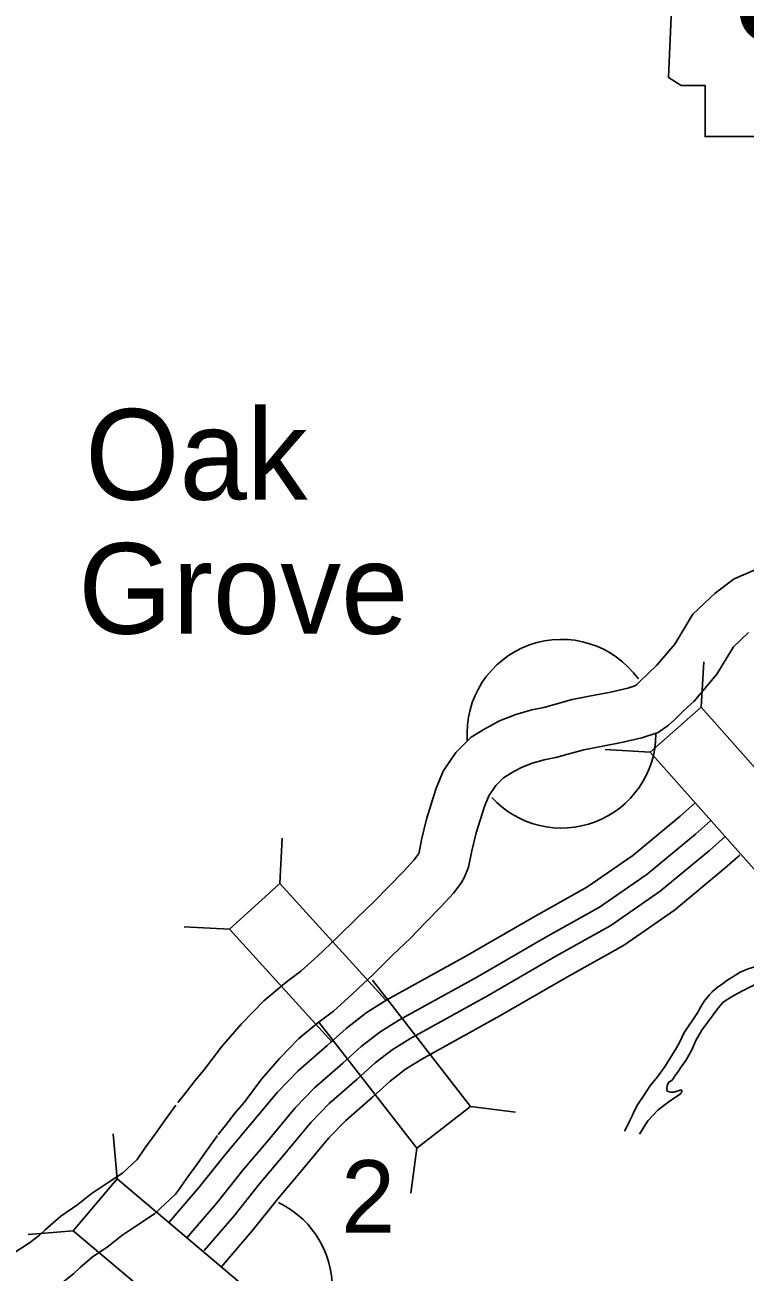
# Model space of a CAD drawing. Extents: x 1373862 to 1377080, y 1164775 to 1170415.
# Drawn here: x 1374523.6 to 1374565.6, y 1170236.6 to 1170309.3 of the extents above; entities that cross this region are included whole.
import ezdxf

# ---------------------------------------------------------------- set-up
doc = ezdxf.new("R2010")
doc.units = 0
doc.layers.add('Default', color=7, linetype='Continuous')

msp = doc.modelspace()

# ---------------------------------------------------------------- linework, layer by layer
at = {"layer": 'Default'}
for p, q in [((1374562.997, 1170269.508), (1374563.156, 1170272.143)), ((1374560.035, 1170266.88), (1374557.399, 1170267.038)), ((1374538.46, 1170259.235), (1374538.588, 1170261.872)), ((1374538.46, 1170259.235), (1374535.528, 1170256.573)), ((1374544.617, 1170252.453), (1374538.46, 1170259.235)), ((1374535.528, 1170256.573), (1374532.891, 1170256.701)), ((1374535.528, 1170256.573), (1374541.501, 1170249.994)), ((1374549.559, 1170246.234), (1374543.849, 1170253.598)), ((1374540.739, 1170251.147), (1374546.43, 1170243.807)), ((1374546.43, 1170243.807), (1374549.559, 1170246.234)), ((1374549.559, 1170246.234), (1374552.178, 1170245.902)), ((1374528.983, 1170242.017), (1374528.761, 1170244.647)), ((1374546.43, 1170243.807), (1374546.098, 1170241.188)), ((1374526.428, 1170238.991), (1374523.798, 1170238.769))]:
    msp.add_line(p, q, dxfattribs=at)
for points in [[(1374560.624, 1170320.259), (1374561.461, 1170314.676), (1374561.089, 1170306.209), (1374561.833, 1170305.744), (1374563.229, 1170305.744), (1374563.229, 1170302.766), (1374574.953, 1170302.766), (1374575.512, 1170303.976), (1374575.325, 1170305.93), (1374575.605, 1170308.163), (1374576.628, 1170309.931), (1374577.279, 1170311.234), (1374578.21, 1170312.629), (1374578.768, 1170314.118), (1374579.233, 1170315.328), (1374580.071, 1170316.351), (1374580.257, 1170317.003), (1374579.885, 1170317.468), (1374577, 1170317.468), (1374577.652, 1170318.77), (1374577.745, 1170319.608), (1374577.359, 1170320.251)], [(1374560.035, 1170266.88), (1374567.917, 1170257.992), (1374570.88, 1170260.619), (1374562.997, 1170269.508)], [(1374538.06, 1170234.352), (1374528.983, 1170242.017), (1374526.428, 1170238.991), (1374535.505, 1170231.326)]]:
    msp.add_lwpolyline(points, close=True, dxfattribs=at)
for points in [[(1374566.864, 1170277.817), (1374564.92, 1170276.994), (1374563.819, 1170276.152), (1374562.511, 1170274.925), (1374561.466, 1170273.176), (1374560.424, 1170271.947), (1374559.902, 1170271.469), (1374559.394, 1170270.96), (1374559.249, 1170270.83), (1374559.131, 1170270.75), (1374558.729, 1170270.613), (1374557.648, 1170270.368), (1374556.891, 1170270.224), (1374555.482, 1170269.947), (1374554.452, 1170269.67), (1374553.826, 1170269.497), (1374553.134, 1170269.348), (1374552.198, 1170269.083), (1374551.258, 1170268.715), (1374550.695, 1170268.407), (1374550.394, 1170268.246), (1374549.601, 1170267.759), (1374548.72, 1170266.86), (1374547.971, 1170265.774), (1374547.553, 1170264.73), (1374547.009, 1170262.983), (1374546.716, 1170261.78), (1374546.566, 1170261.035), (1374546.523, 1170260.929), (1374546.265, 1170260.595), (1374545.673, 1170259.945), (1374544.786, 1170259.031), (1374543.955, 1170258.183), (1374542.941, 1170257.218), (1374541.822, 1170256.096), (1374540.634, 1170254.978), (1374539.681, 1170254.114), (1374538.822, 1170253.476), (1374537.529, 1170252.397), (1374536.234, 1170251.063), (1374535.061, 1170249.719), (1374534.038, 1170248.347), (1374533.532, 1170247.754), (1374532.922, 1170246.965), (1374532.525, 1170246.463)], [(1374565.762, 1170273.861), (1374564.87, 1170273.024), (1374563.914, 1170271.425), (1374562.59, 1170269.862), (1374561.977, 1170269.301), (1374561.459, 1170268.782), (1374561.103, 1170268.463), (1374560.484, 1170268.042), (1374559.547, 1170267.722), (1374558.26, 1170267.43), (1374557.46, 1170267.278), (1374556.161, 1170267.023), (1374555.241, 1170266.776), (1374554.542, 1170266.583), (1374553.859, 1170266.435), (1374553.156, 1170266.237), (1374552.529, 1170265.991), (1374552.125, 1170265.77), (1374551.892, 1170265.644), (1374551.485, 1170265.395), (1374551.043, 1170264.944), (1374550.631, 1170264.347), (1374550.382, 1170263.724), (1374549.901, 1170262.182), (1374549.645, 1170261.129), (1374549.453, 1170260.175), (1374549.205, 1170259.553), (1374549.007, 1170259.236), (1374548.565, 1170258.664), (1374547.859, 1170257.889), (1374546.934, 1170256.936), (1374546.061, 1170256.046), (1374545.037, 1170255.071), (1374543.912, 1170253.944), (1374542.67, 1170252.775), (1374541.587, 1170251.792), (1374540.678, 1170251.118), (1374539.572, 1170250.194), (1374538.442, 1170249.031), (1374537.397, 1170247.833), (1374536.384, 1170246.474), (1374535.861, 1170245.862), (1374535.285, 1170245.117), (1374534.877, 1170244.601)], [(1374562.625, 1170263.911), (1374561.77, 1170263.153), (1374559.015, 1170260.871), (1374556.346, 1170259.018), (1374553.226, 1170257.278), (1374549.294, 1170254.992), (1374544.695, 1170252.444), (1374543.491, 1170251.692), (1374542.315, 1170250.781), (1374541.225, 1170249.783), (1374539.534, 1170248.319), (1374538.33, 1170247.079), (1374536.724, 1170245.139), (1374535.247, 1170243.388), (1374533.772, 1170241.532), (1374532.013, 1170239.494)], [(1374563.542, 1170262.886), (1374562.665, 1170262.109), (1374559.847, 1170259.775), (1374557.075, 1170257.85), (1374553.907, 1170256.083), (1374549.973, 1170253.796), (1374545.392, 1170251.259), (1374544.279, 1170250.563), (1374543.202, 1170249.728), (1374542.139, 1170248.756), (1374540.48, 1170247.318), (1374539.355, 1170246.16), (1374537.779, 1170244.257), (1374536.311, 1170242.517), (1374534.831, 1170240.655), (1374533.049, 1170238.591)], [(1374564.385, 1170261.964), (1374563.478, 1170261.16), (1374560.604, 1170258.778), (1374557.738, 1170256.789), (1374554.525, 1170254.997), (1374550.59, 1170252.709), (1374546.027, 1170250.181), (1374544.995, 1170249.537), (1374544.008, 1170248.771), (1374542.97, 1170247.823), (1374541.339, 1170246.409), (1374540.286, 1170245.325), (1374538.738, 1170243.456), (1374537.278, 1170241.725), (1374535.794, 1170239.857), (1374534.048, 1170237.834)], [(1374565.245, 1170260.889), (1374564.373, 1170260.116), (1374561.436, 1170257.682), (1374558.466, 1170255.621), (1374555.206, 1170253.802), (1374551.269, 1170251.513), (1374546.725, 1170248.996), (1374545.782, 1170248.407), (1374544.895, 1170247.719), (1374543.885, 1170246.796), (1374542.284, 1170245.408), (1374541.31, 1170244.406), (1374539.793, 1170242.574), (1374538.342, 1170240.854), (1374536.853, 1170238.98), (1374535.038, 1170236.878)], [(1374568.834, 1170254.97), (1374568.628, 1170254.922), (1374568.259, 1170254.889), (1374567.72, 1170254.804), (1374567.242, 1170254.7), (1374566.266, 1170254.411), (1374565.738, 1170254.266), (1374565.26, 1170254.062), (1374564.833, 1170253.798), (1374564.545, 1170253.615), (1374564.238, 1170253.382), (1374563.92, 1170253.169), (1374563.632, 1170252.916), (1374563.484, 1170252.745), (1374563.178, 1170252.372), (1374562.921, 1170251.949), (1374562.813, 1170251.748), (1374561.985, 1170250.509), (1374561.749, 1170250.006), (1374561.562, 1170249.664), (1374561.356, 1170249.302), (1374560.892, 1170248.577), (1374560.448, 1170247.962)], [(1374566.145, 1170253.349), (1374565.439, 1170253.002), (1374564.902, 1170252.697), (1374564.385, 1170252.402), (1374564.237, 1170252.271), (1374563.911, 1170251.867), (1374563.417, 1170251.202), (1374563.032, 1170250.688), (1374562.687, 1170250.084), (1374562.452, 1170249.531), (1374562.098, 1170248.918), (1374561.802, 1170248.484), (1374561.634, 1170248.243), (1374561.525, 1170248.101), (1374561.348, 1170247.83), (1374561.279, 1170247.759), (1374561.12, 1170247.657), (1374561.061, 1170247.557), (1374561.012, 1170247.416), (1374561.003, 1170247.316), (1374561.004, 1170247.186), (1374561.044, 1170247.126), (1374561.134, 1170247.087), (1374561.214, 1170247.067), (1374561.424, 1170247.079), (1374561.573, 1170247.12), (1374561.673, 1170247.151), (1374561.782, 1170247.182), (1374561.862, 1170247.193), (1374561.863, 1170247.113), (1374561.804, 1170247.002), (1374561.655, 1170246.881), (1374561.387, 1170246.708), (1374560.97, 1170246.404), (1374560.484, 1170246.04), (1374559.9, 1170245.404), (1374559.555, 1170244.88), (1374559.413, 1170244.627)], [(1374560.448, 1170247.962), (1374560.003, 1170247.417), (1374559.658, 1170246.884), (1374559.293, 1170246.34), (1374559.116, 1170246.008), (1374558.989, 1170245.726), (1374558.822, 1170245.374), (1374558.645, 1170245.002), (1374558.557, 1170244.831), (1374558.542, 1170244.799)], [(1374532.405, 1170246.306), (1374531.748, 1170245.405), (1374531.234, 1170244.674), (1374530.608, 1170243.802), (1374530.147, 1170243.143)], [(1374534.829, 1170244.538), (1374534.187, 1170243.658), (1374533.68, 1170242.937), (1374533.056, 1170242.068), (1374532.621, 1170241.445), (1374532.386, 1170241.129)], [(1374524.788, 1170239.053), (1374525.71, 1170239.842), (1374526.7, 1170240.516), (1374527.481, 1170241.14), (1374528.465, 1170241.797), (1374529.295, 1170242.35), (1374530.147, 1170243.143)], [(1374526.828, 1170236.85), (1374527.535, 1170237.456), (1374528.483, 1170238.1), (1374529.253, 1170238.716), (1374530.129, 1170239.301), (1374531.161, 1170239.988), (1374532.386, 1170241.129)], [(1374518.677, 1170235.385), (1374519.448, 1170235.728), (1374520.876, 1170236.299), (1374522.076, 1170237.111), (1374523.056, 1170237.738), (1374523.89, 1170238.282), (1374524.465, 1170238.729), (1374524.788, 1170239.053)], [(1374519.577, 1170232.502), (1374520.616, 1170232.964), (1374522.289, 1170233.633), (1374523.725, 1170234.605), (1374524.684, 1170235.218), (1374525.633, 1170235.837), (1374526.454, 1170236.476), (1374526.828, 1170236.85)]]:
    msp.add_lwpolyline(points, dxfattribs=at)
for centre, start, end in [((1374554.861, 1170267.96), 35.46278, 184.16709), ((1374554.861, 1170267.96), 222.40975, 359.67666), ((1374536.009, 1170235.678), 213.32986, 64.30591)]:
    msp.add_arc(centre, 5.5, start, end, dxfattribs=at)

# ---------------------------------------------------------------- texts
for s, height, p in [('84', 6.9696, (1374564.827, 1170308.254)), ('Oak', 5.28, (1374527.124, 1170281.605)), ('Grove', 5.28, (1374526.722, 1170273.79)), ('2', 4.224, (1374542.034, 1170238.881))]:
    msp.add_text(s, height=height, dxfattribs=at).set_placement(p)

doc.saveas('drawing.dxf')
